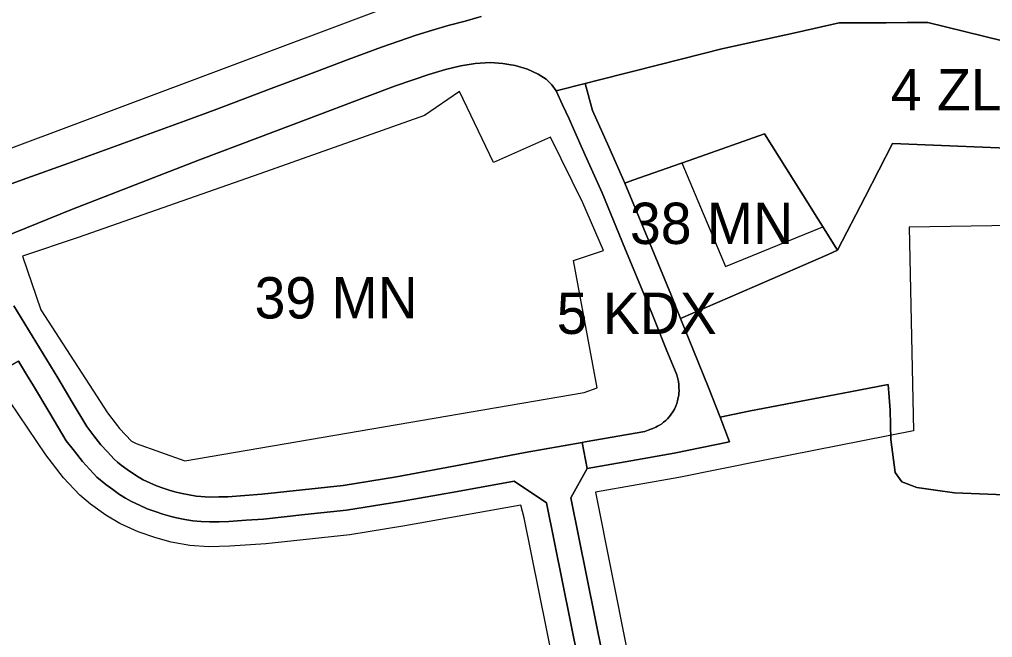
# Model space of a CAD drawing. Extents: x 7423432 to 7425824, y 5537848 to 5539677.
# Drawn here: x 7424420.7 to 7424655.7, y 5539125.1 to 5539274.6 of the extents above; entities that cross this region are included whole.
import ezdxf

# ---------------------------------------------------------------- set-up
doc = ezdxf.new("R2010")
doc.units = 0
for name, color, linetype in [('linie_rozgraniczajace', 7, 'Continuous'), ('linie_zabudowy_nieprzekraczalne', 7, 'Continuous'), ('oznaczenia_przeznaczen', 7, 'Continuous')]:
    doc.layers.add(name, color=color, linetype=linetype)

msp = doc.modelspace()

# ---------------------------------------------------------------- linework, layer by layer
at = {"layer": 'linie_rozgraniczajace'}
for points in [[(7424532.21, 5539275.26), (7424528.28, 5539274.19), (7424524.23, 5539273.09), (7424520.42, 5539271.95), (7424516.49, 5539270.78), (7424512.31, 5539269.34), (7424508.13, 5539267.9), (7424500.08, 5539264.88), (7424492.03, 5539261.85), (7424486.89, 5539259.91), (7424480.8, 5539257.62), (7424474.71, 5539255.32), (7424467.71, 5539252.67), (7424460.7, 5539250.02), (7424446.51, 5539244.87), (7424432.32, 5539239.71), (7424422.43, 5539236.19), (7424411.9, 5539232.41)], [(7424411.9, 5539232.41), (7424422.43, 5539236.19), (7424432.32, 5539239.71), (7424446.51, 5539244.87), (7424460.7, 5539250.02), (7424467.71, 5539252.67), (7424474.71, 5539255.32), (7424480.8, 5539257.62), (7424486.89, 5539259.91), (7424492.03, 5539261.85), (7424500.08, 5539264.88), (7424508.13, 5539267.9), (7424512.31, 5539269.34), (7424516.49, 5539270.78), (7424520.42, 5539271.95), (7424524.23, 5539273.09), (7424528.28, 5539274.19), (7424532.21, 5539275.26)], [(7424658.13, 5539269.37), (7424640.06, 5539273.83), (7424635.04, 5539273.8), (7424630.03, 5539273.78), (7424624.36, 5539273.75), (7424618.69, 5539273.72), (7424608.35, 5539271.43), (7424598.02, 5539269.14), (7424590.35, 5539267.45), (7424575.41, 5539263.68), (7424560.47, 5539259.91), (7424557.29, 5539259.09), (7424550.27, 5539257.28), (7424549.28, 5539258.77), (7424547.85, 5539260.1), (7424545.98, 5539261.34), (7424543.37, 5539262.53), (7424540.37, 5539263.42), (7424538.89, 5539263.69), (7424537.41, 5539263.96), (7424534.34, 5539264.15), (7424530.73, 5539263.95), (7424527.24, 5539263.38), (7424523.6, 5539262.46), (7424519.55, 5539261.26), (7424511.52, 5539258.49), (7424504.04, 5539255.68), (7424490.42, 5539250.56), (7424478.25, 5539245.96), (7424464.18, 5539240.65), (7424448.61, 5539234.58), (7424433.05, 5539228.52), (7424424.93, 5539225.23), (7424416.82, 5539221.95)], [(7424659.17, 5539243.47), (7424645.36, 5539244.01), (7424631.55, 5539244.55), (7424624.91, 5539231.66), (7424618.27, 5539218.77), (7424609.45, 5539232.85), (7424600.62, 5539246.94), (7424583.75, 5539240.98), (7424568.79, 5539235.7), (7424566.88, 5539235.03), (7424562.98, 5539243.81), (7424559.07, 5539252.59), (7424557.29, 5539259.09), (7424560.47, 5539259.91), (7424575.41, 5539263.68), (7424590.35, 5539267.45), (7424598.02, 5539269.14), (7424608.35, 5539271.43), (7424618.69, 5539273.72), (7424624.36, 5539273.75), (7424630.03, 5539273.78), (7424635.04, 5539273.8), (7424640.06, 5539273.83), (7424658.13, 5539269.37)], [(7424416.82, 5539221.95), (7424424.93, 5539225.23), (7424433.05, 5539228.52), (7424448.61, 5539234.58), (7424464.18, 5539240.65), (7424478.25, 5539245.96), (7424490.42, 5539250.56), (7424504.04, 5539255.68), (7424511.52, 5539258.49), (7424519.55, 5539261.26), (7424523.6, 5539262.46), (7424527.24, 5539263.38), (7424530.73, 5539263.95), (7424534.34, 5539264.15), (7424537.41, 5539263.96), (7424538.89, 5539263.69), (7424540.37, 5539263.42), (7424543.37, 5539262.53), (7424545.98, 5539261.34), (7424547.85, 5539260.1), (7424549.28, 5539258.77), (7424550.27, 5539257.28), (7424551.84, 5539253.92), (7424553.4, 5539250.56), (7424554.49, 5539248.11), (7424557.34, 5539241.72), (7424561.37, 5539232.66), (7424566.9, 5539219.28), (7424572.42, 5539205.9), (7424573.38, 5539203.54), (7424574.33, 5539201.18), (7424576.87, 5539194.9), (7424579.41, 5539188.63), (7424579.82, 5539187.07), (7424579.89, 5539186.32), (7424579.95, 5539185.57), (7424579.97, 5539184.75), (7424579.94, 5539184.2), (7424579.89, 5539183.72), (7424579.8, 5539183.14), (7424579.64, 5539182.4), (7424579.42, 5539181.7), (7424579.18, 5539181.07), (7424578.86, 5539180.37), (7424578.49, 5539179.72), (7424578.1, 5539179.14), (7424577.65, 5539178.55), (7424577.19, 5539178.04), (7424576.78, 5539177.63), (7424576.25, 5539177.18), (7424575.81, 5539176.84), (7424575.26, 5539176.47), (7424574.81, 5539176.21), (7424574.4, 5539175.99), (7424573.65, 5539175.66), (7424573.2, 5539175.5), (7424572.5, 5539175.25), (7424571.75, 5539174.99), (7424557.26, 5539172.43), (7424556.54, 5539172.3), (7424542.77, 5539169.87), (7424527.25, 5539166.93), (7424511.73, 5539163.98), (7424505.28, 5539162.94), (7424498.84, 5539161.91), (7424489.01, 5539160.84), (7424479.19, 5539159.77), (7424475.08, 5539159.48), (7424470.97, 5539159.19), (7424468.81, 5539159.15), (7424466.64, 5539159.11), (7424463.31, 5539159.3), (7424461.64, 5539159.62), (7424459.97, 5539159.94), (7424458.51, 5539160.33), (7424457.05, 5539160.73), (7424455.4, 5539161.28), (7424453.74, 5539161.84), (7424452.13, 5539162.58), (7424450.51, 5539163.31), (7424449.34, 5539164.03), (7424448.17, 5539164.74), (7424446.68, 5539165.8), (7424445.2, 5539166.85), (7424444.37, 5539167.56), (7424443.54, 5539168.27), (7424441.91, 5539170.02), (7424440.28, 5539171.77), (7424438.6, 5539173.95), (7424436.92, 5539176.13), (7424433.39, 5539182.03), (7424429.91, 5539187.95), (7424424.59, 5539196.66), (7424419.28, 5539205.37)], [(7424660.59, 5539159.56), (7424646.47, 5539160.1), (7424641.95, 5539160.77), (7424637.42, 5539161.43), (7424633.77, 5539162.8), (7424632.17, 5539165.08), (7424631.13, 5539173.01), (7424631.04, 5539176.56), (7424630.94, 5539180.11), (7424630.72, 5539183.22), (7424630.5, 5539186.34), (7424625.92, 5539185.46), (7424621.34, 5539184.58), (7424614.53, 5539183.27), (7424605.66, 5539181.57), (7424596.8, 5539179.86), (7424589.88, 5539178.4), (7424587.1, 5539185.62), (7424583.5, 5539194.52), (7424580.36, 5539202.27), (7424598.24, 5539210.05), (7424615.98, 5539217.78), (7424618.27, 5539218.77), (7424624.91, 5539231.66), (7424631.55, 5539244.55), (7424645.36, 5539244.01), (7424659.17, 5539243.47)], [(7424428.03, 5539179.36), (7424424.08, 5539186.01), (7424422.39, 5539188.75), (7424420.41, 5539191.98), (7424418.64, 5539190.92), (7424412.67, 5539201.63), (7424408.34, 5539209.39), (7424406.7, 5539212.34)], [(7424419.28, 5539205.37), (7424424.59, 5539196.66), (7424429.91, 5539187.95), (7424433.39, 5539182.03), (7424436.92, 5539176.13), (7424438.6, 5539173.95), (7424440.28, 5539171.77), (7424441.91, 5539170.02), (7424443.54, 5539168.27), (7424444.37, 5539167.56), (7424445.2, 5539166.85), (7424446.68, 5539165.8), (7424448.17, 5539164.74), (7424449.34, 5539164.03), (7424450.51, 5539163.31), (7424452.13, 5539162.58), (7424453.74, 5539161.84), (7424455.4, 5539161.28), (7424457.05, 5539160.73), (7424458.51, 5539160.33), (7424459.97, 5539159.94), (7424461.64, 5539159.62), (7424463.31, 5539159.3), (7424466.64, 5539159.11), (7424468.81, 5539159.15), (7424470.97, 5539159.19), (7424475.08, 5539159.48), (7424479.19, 5539159.77), (7424489.01, 5539160.84), (7424498.84, 5539161.91), (7424505.28, 5539162.94), (7424511.73, 5539163.98), (7424527.25, 5539166.93), (7424542.77, 5539169.87), (7424556.54, 5539172.3), (7424557.77, 5539166.03), (7424553.86, 5539158.95), (7424557.72, 5539139.78), (7424561.59, 5539120.6)], [(7424420.41, 5539191.98), (7424422.39, 5539188.75), (7424424.08, 5539186.01), (7424428.03, 5539179.36), (7424431.97, 5539172.72), (7424433.93, 5539170.2), (7424435.89, 5539167.68), (7424437.64, 5539165.81), (7424439.38, 5539163.94), (7424441.5, 5539162.12), (7424443.18, 5539160.92), (7424444.86, 5539159.73), (7424446.28, 5539158.86), (7424447.7, 5539158), (7424449.62, 5539157.13), (7424451.53, 5539156.26), (7424453.42, 5539155.62), (7424455.31, 5539154.98), (7424456.96, 5539154.53), (7424458.62, 5539154.09), (7424460.6, 5539153.71), (7424462.57, 5539153.33), (7424464.55, 5539153.22), (7424466.53, 5539153.1), (7424468.88, 5539153.15), (7424471.24, 5539153.19), (7424475.42, 5539153.49), (7424479.61, 5539153.78), (7424489.62, 5539154.87), (7424499.64, 5539155.96), (7424506.18, 5539157.01), (7424512.73, 5539158.06), (7424526.45, 5539160.49), (7424540.18, 5539162.92), (7424547.98, 5539157.74), (7424551.85, 5539138.56), (7424555.72, 5539119.38)], [(7424561.59, 5539120.6), (7424557.72, 5539139.78), (7424553.86, 5539158.95), (7424557.77, 5539166.03), (7424568.3, 5539167.89), (7424578.83, 5539169.75), (7424585.5, 5539171.1), (7424592.18, 5539172.44), (7424589.88, 5539178.4), (7424596.8, 5539179.86), (7424605.66, 5539181.57), (7424614.53, 5539183.27), (7424621.34, 5539184.58), (7424625.92, 5539185.46), (7424630.5, 5539186.34), (7424630.72, 5539183.22), (7424630.94, 5539180.11), (7424631.04, 5539176.56), (7424631.13, 5539173.01), (7424632.17, 5539165.08), (7424633.77, 5539162.8), (7424637.42, 5539161.43), (7424641.95, 5539160.77), (7424646.47, 5539160.1), (7424660.59, 5539159.56)], [(7424555.72, 5539119.38), (7424551.85, 5539138.56), (7424547.98, 5539157.74), (7424540.18, 5539162.92), (7424526.45, 5539160.49), (7424512.73, 5539158.06), (7424506.18, 5539157.01), (7424499.64, 5539155.96), (7424489.62, 5539154.87), (7424479.61, 5539153.78), (7424475.42, 5539153.49), (7424471.24, 5539153.19), (7424468.88, 5539153.15), (7424466.53, 5539153.1), (7424464.55, 5539153.22), (7424462.57, 5539153.33), (7424460.6, 5539153.71), (7424458.62, 5539154.09), (7424456.96, 5539154.53), (7424455.31, 5539154.98), (7424453.42, 5539155.62), (7424451.53, 5539156.26), (7424449.62, 5539157.13), (7424447.7, 5539158), (7424446.28, 5539158.86), (7424444.86, 5539159.73), (7424443.18, 5539160.92), (7424441.5, 5539162.12), (7424439.38, 5539163.94), (7424437.64, 5539165.81), (7424435.89, 5539167.68), (7424433.93, 5539170.2), (7424431.97, 5539172.72), (7424428.03, 5539179.36)]]:
    msp.add_lwpolyline(points, dxfattribs=at)
for points in [[(7424550.27, 5539257.28), (7424557.29, 5539259.09), (7424559.07, 5539252.59), (7424562.98, 5539243.81), (7424566.88, 5539235.03), (7424572.43, 5539221.6), (7424577.98, 5539208.16), (7424580.36, 5539202.27), (7424583.5, 5539194.52), (7424587.1, 5539185.62), (7424589.88, 5539178.4), (7424592.18, 5539172.44), (7424585.5, 5539171.1), (7424578.83, 5539169.75), (7424568.3, 5539167.89), (7424557.77, 5539166.03), (7424556.54, 5539172.3), (7424557.26, 5539172.43), (7424571.75, 5539174.99), (7424572.5, 5539175.25), (7424573.2, 5539175.5), (7424573.65, 5539175.66), (7424574.4, 5539175.99), (7424574.81, 5539176.21), (7424575.26, 5539176.47), (7424575.81, 5539176.84), (7424576.25, 5539177.18), (7424576.78, 5539177.63), (7424577.19, 5539178.04), (7424577.65, 5539178.55), (7424578.1, 5539179.14), (7424578.49, 5539179.72), (7424578.86, 5539180.37), (7424579.18, 5539181.07), (7424579.42, 5539181.7), (7424579.64, 5539182.4), (7424579.8, 5539183.14), (7424579.89, 5539183.72), (7424579.94, 5539184.2), (7424579.97, 5539184.75), (7424579.95, 5539185.57), (7424579.89, 5539186.32), (7424579.82, 5539187.07), (7424579.41, 5539188.63), (7424576.87, 5539194.9), (7424574.33, 5539201.18), (7424573.38, 5539203.54), (7424572.42, 5539205.9), (7424566.9, 5539219.28), (7424561.37, 5539232.66), (7424557.34, 5539241.72), (7424554.49, 5539248.11), (7424553.4, 5539250.56), (7424551.84, 5539253.92)], [(7424566.88, 5539235.03), (7424568.79, 5539235.7), (7424583.75, 5539240.98), (7424600.62, 5539246.94), (7424609.45, 5539232.85), (7424618.27, 5539218.77), (7424615.98, 5539217.78), (7424598.24, 5539210.05), (7424580.36, 5539202.27), (7424577.98, 5539208.16), (7424572.43, 5539221.6)]]:
    msp.add_lwpolyline(points, close=True, dxfattribs=at)
at = {"layer": 'linie_zabudowy_nieprzekraczalne'}
for points in [[(7424409.7, 5539240.15), (7424537.69, 5539288.2)], [(7424548.9, 5539246.13), (7424535.14, 5539239.97), (7424526.95, 5539257.12), (7424526.95, 5539257.12), (7424526.95, 5539257.12), (7424518.53, 5539251.36), (7424518.53, 5539251.36), (7424518.53, 5539251.36), (7424518.53, 5539251.36), (7424518.53, 5539251.36), (7424478.72, 5539237.28), (7424434.85, 5539221.84), (7424421.36, 5539217.32), (7424425.86, 5539204.34), (7424425.86, 5539204.34), (7424425.86, 5539204.34), (7424441.89, 5539179.51), (7424441.89, 5539179.51), (7424444.86, 5539175.65), (7424447.7, 5539172.61), (7424447.7, 5539172.61), (7424448.84, 5539172.03), (7424460.63, 5539167.83), (7424460.63, 5539167.83), (7424460.63, 5539167.83), (7424460.63, 5539167.83), (7424460.63, 5539167.83), (7424460.63, 5539167.83), (7424460.63, 5539167.83), (7424460.63, 5539167.83), (7424460.63, 5539167.83), (7424557.05, 5539184.37), (7424557.05, 5539184.37), (7424557.05, 5539184.37), (7424560.17, 5539185.49), (7424554.5, 5539216.32), (7424561.76, 5539218.69), (7424556.7, 5539230.24), (7424548.9, 5539246.13)], [(7424580.61, 5539239.87), (7424591.17, 5539214.86), (7424614.73, 5539224.43)], [(7424831.74, 5539197.29), (7424787.27, 5539208.2), (7424735.74, 5539213.07), (7424735.94, 5539226.27), (7424715.38, 5539225.61), (7424635.55, 5539224.39), (7424636.63, 5539175.13), (7424600.33, 5539167.96), (7424579.95, 5539163.86), (7424559.78, 5539160.29), (7424567.47, 5539121.83)], [(7424549.84, 5539118.15), (7424542.59, 5539154.11), (7424541.79, 5539157.11), (7424513.72, 5539152.15), (7424500.44, 5539150.01), (7424480.14, 5539147.8), (7424471.51, 5539147.2), (7424466.42, 5539147.1), (7424461.84, 5539147.36), (7424457.27, 5539148.24), (7424453.56, 5539149.24), (7424449.32, 5539150.67), (7424444.89, 5539152.69), (7424441.56, 5539154.72), (7424437.8, 5539157.39), (7424435.22, 5539159.6), (7424431.32, 5539163.79), (7424427.01, 5539169.33), (7424418.37, 5539182.22)]]:
    msp.add_lwpolyline(points, dxfattribs=at)

# ---------------------------------------------------------------- texts
at = {"layer": 'oznaczenia_przeznaczen'}
for s, p in [('4 ZL', (7424631.14, 5539252.56)), ('38 MN', (7424568.12, 5539220.28)), ('39 MN', (7424477.46, 5539202.28)), ('5 KDX', (7424550.43, 5539198.54))]:
    msp.add_text(s, height=10, dxfattribs=at).set_placement(p)

doc.saveas('drawing.dxf')
